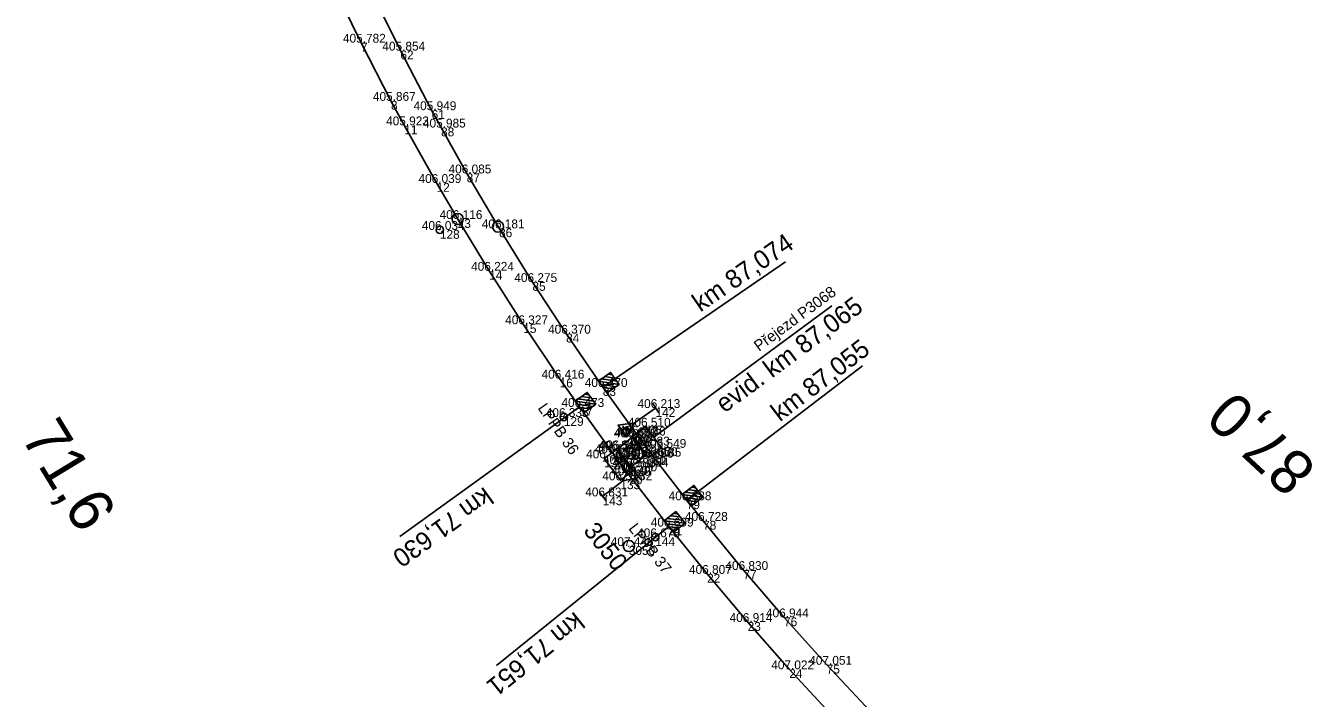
# Model space of a CAD drawing. Extents: x -663503 to -663109, y -1005607 to -1005191.
# Drawn here: x -663458.2 to -663283.9, y -1005429.6 to -1005338.4 of the extents above; entities that cross this region are included whole.
import ezdxf

# ---------------------------------------------------------------- set-up
doc = ezdxf.new("R2010")
doc.units = 0
for name, color, linetype in [('Vrstva 1', 7, 'Continuous'), ('Vrstva 27', 7, 'Continuous'), ('Vrstva 3', 7, 'Continuous'), ('Vrstva 4', 7, 'Continuous'), ('Vrstva 51', 7, 'Continuous'), ('Vrstva 60', 7, 'Continuous'), ('Vrstva 61', 7, 'Continuous'), ('Vrstva 63', 7, 'Continuous'), ('Vrstva 7', 7, 'Continuous')]:
    doc.layers.add(name, color=color, linetype=linetype)

msp = doc.modelspace()

# ---------------------------------------------------------------- linework, layer by layer
at = {"layer": 'Vrstva 1'}
for points in [[(-663416.55, -1005332.92), (-663412.77, -1005340.68), (-663408.71, -1005348.57), (-663406.91, -1005351.89), (-663402.53, -1005359.71), (-663399.67, -1005364.6), (-663395.4, -1005371.62), (-663390.78, -1005378.87), (-663385.85, -1005386.25), (-663383.15, -1005390.1), (-663378.63, -1005396.38), (-663377.54, -1005397.85), (-663376.41, -1005399.36), (-663371.04, -1005406.33), (-663365.87, -1005412.74), (-663360.37, -1005419.27), (-663354.73, -1005425.68), (-663349.15, -1005431.73)], [(-663343.71, -1005431.4), (-663349.66, -1005425.07), (-663355.44, -1005418.64), (-663360.94, -1005412.22), (-663366.41, -1005405.55), (-663368.63, -1005402.76), (-663373.21, -1005396.77), (-663374.28, -1005395.33), (-663375.38, -1005393.84), (-663380, -1005387.39), (-663384.97, -1005380.15), (-663389.54, -1005373.15), (-663394.06, -1005365.86), (-663398.45, -1005358.41), (-663401.92, -1005352.19), (-663403.2, -1005349.83), (-663407.43, -1005341.75), (-663411.05, -1005334.42)]]:
    msp.add_lwpolyline(points, dxfattribs=at)
at = {"layer": 'Vrstva 27'}
for p, q in [((-663385.3, -1005391.42), (-663385.25, -1005391.5)), ((-663372.92, -1005407.73), (-663372.86, -1005407.81))]:
    msp.add_line(p, q, dxfattribs=at)
for centre in [(-663385.28, -1005391.46), (-663372.89, -1005407.77)]:
    msp.add_circle(centre, 0.5, dxfattribs=at)
at = {"layer": 'Vrstva 3'}
for p, q in [((-663355.26, -1005370.41), (-663380, -1005387.39)), ((-663344.79, -1005384.54), (-663368.63, -1005402.76)), ((-663378.1, -1005386.61), (-663380.15, -1005386.27)), ((-663378.41, -1005386.18), (-663379.72, -1005385.96)), ((-663378.72, -1005385.74), (-663379.29, -1005385.65)), ((-663377.79, -1005387.04), (-663380.58, -1005386.58)), ((-663378.22, -1005387.35), (-663380.27, -1005387.01)), ((-663378.65, -1005387.66), (-663379.96, -1005387.44)), ((-663379.08, -1005387.96), (-663379.65, -1005387.87)), ((-663380.95, -1005389.74), (-663383.74, -1005389.29)), ((-663381.38, -1005390.05), (-663383.43, -1005389.72)), ((-663381.26, -1005389.31), (-663383.31, -1005388.98)), ((-663381.57, -1005388.88), (-663382.88, -1005388.67)), ((-663381.88, -1005388.45), (-663382.45, -1005388.36)), ((-663383.15, -1005390.1), (-663407.49, -1005407.65)), ((-663381.81, -1005390.37), (-663383.12, -1005390.15)), ((-663382.24, -1005390.68), (-663382.81, -1005390.58)), ((-663366.43, -1005402.33), (-663369.24, -1005401.97)), ((-663366.76, -1005401.91), (-663368.82, -1005401.65)), ((-663367.08, -1005401.49), (-663368.4, -1005401.32)), ((-663367.41, -1005401.07), (-663367.98, -1005401)), ((-663366.85, -1005402.65), (-663368.91, -1005402.39)), ((-663367.27, -1005402.98), (-663368.59, -1005402.81)), ((-663367.69, -1005403.3), (-663368.26, -1005403.23)), ((-663368.86, -1005405.85), (-663371.67, -1005405.55)), ((-663369.19, -1005405.44), (-663371.26, -1005405.21)), ((-663369.53, -1005405.02), (-663370.85, -1005404.88)), ((-663369.86, -1005404.61), (-663370.43, -1005404.55)), ((-663371.04, -1005406.33), (-663394.39, -1005425.16)), ((-663369.27, -1005406.18), (-663371.34, -1005405.96)), ((-663369.69, -1005406.51), (-663371.01, -1005406.37)), ((-663370.1, -1005406.85), (-663370.67, -1005406.78))]:
    msp.add_line(p, q, dxfattribs=at)
for points in [[(-663379.42, -1005388.2), (-663380.58, -1005386.58), (-663378.95, -1005385.41), (-663377.79, -1005387.04)], [(-663382.57, -1005390.91), (-663383.74, -1005389.29), (-663382.12, -1005388.12), (-663380.95, -1005389.74)], [(-663368.01, -1005403.55), (-663369.24, -1005401.97), (-663367.66, -1005400.75), (-663366.43, -1005402.33)], [(-663370.42, -1005407.1), (-663371.67, -1005405.55), (-663370.12, -1005404.29), (-663368.86, -1005405.85)]]:
    msp.add_lwpolyline(points, close=True, dxfattribs=at)
at = {"layer": 'Vrstva 4'}
for p, q in [((-663348.97, -1005376.37), (-663373.1, -1005394.2)), ((-663372.41, -1005390.88), (-663373.29, -1005389.6)), ((-663376.56, -1005393.09), (-663377.04, -1005393)), ((-663376.45, -1005399.22), (-663375.96, -1005399.28)), ((-663380.5, -1005401.61), (-663379.55, -1005402.84))]:
    msp.add_line(p, q, dxfattribs=at)
for points in [[(-663372.85, -1005390.24), (-663375.7, -1005392.23), (-663376.78, -1005394.19), (-663377.93, -1005392.56), (-663375.7, -1005392.23)], [(-663374.16, -1005392.77), (-663375.93, -1005394.08), (-663373.8, -1005396.98), (-663372.04, -1005395.64), (-663374.16, -1005392.77)], [(-663379.81, -1005397.07), (-663378.18, -1005395.92), (-663375.99, -1005398.83), (-663377.62, -1005400.05), (-663379.81, -1005397.07)], [(-663380.03, -1005402.23), (-663377.27, -1005400.11), (-663376.28, -1005398.1), (-663375.06, -1005399.68), (-663377.27, -1005400.11)]]:
    msp.add_lwpolyline(points, dxfattribs=at)
for centre in [(-663376.8, -1005393.04), (-663376.21, -1005399.25)]:
    msp.add_circle(centre, 0.248, dxfattribs=at)
at = {"layer": 'Vrstva 51'}
msp.add_lwpolyline([(-663378, -1005395.83), (-663376.06, -1005394.22), (-663374.22, -1005396.7), (-663376.2, -1005398.24), (-663378, -1005395.83)], dxfattribs=at)
at = {"layer": 'Vrstva 60'}
for p, q in [((-663412.77, -1005340.68), (-663412.77, -1005340.68)), ((-663407.43, -1005341.75), (-663407.43, -1005341.75)), ((-663408.71, -1005348.57), (-663408.71, -1005348.57)), ((-663403.2, -1005349.83), (-663403.2, -1005349.83)), ((-663406.91, -1005351.89), (-663406.91, -1005351.89)), ((-663401.92, -1005352.19), (-663401.92, -1005352.19)), ((-663398.45, -1005358.41), (-663398.45, -1005358.41)), ((-663402.53, -1005359.71), (-663402.53, -1005359.71)), ((-663399.67, -1005364.6), (-663399.67, -1005364.6)), ((-663402.08, -1005366.08), (-663402.08, -1005366.08)), ((-663394.06, -1005365.86), (-663394.06, -1005365.86)), ((-663395.4, -1005371.62), (-663395.4, -1005371.62)), ((-663389.54, -1005373.15), (-663389.54, -1005373.15)), ((-663390.78, -1005378.87), (-663390.78, -1005378.87)), ((-663384.97, -1005380.15), (-663384.97, -1005380.15)), ((-663385.85, -1005386.25), (-663385.85, -1005386.25)), ((-663380, -1005387.39), (-663380, -1005387.39)), ((-663385.28, -1005391.46), (-663385.28, -1005391.46)), ((-663383.15, -1005390.1), (-663383.15, -1005390.1)), ((-663372.85, -1005390.24), (-663372.85, -1005390.24)), ((-663374.16, -1005392.77), (-663374.16, -1005392.77)), ((-663376.06, -1005394.22), (-663376.06, -1005394.22)), ((-663375.93, -1005394.08), (-663375.93, -1005394.08)), ((-663375.38, -1005393.84), (-663375.38, -1005393.84)), ((-663378.63, -1005396.38), (-663378.63, -1005396.38)), ((-663378.18, -1005395.92), (-663378.18, -1005395.92)), ((-663378, -1005395.83), (-663378, -1005395.83)), ((-663374.28, -1005395.33), (-663374.28, -1005395.33)), ((-663374.22, -1005396.7), (-663374.22, -1005396.7)), ((-663373.21, -1005396.77), (-663373.21, -1005396.77)), ((-663372.04, -1005395.64), (-663372.04, -1005395.64)), ((-663379.81, -1005397.07), (-663379.81, -1005397.07)), ((-663377.54, -1005397.85), (-663377.54, -1005397.85)), ((-663376.2, -1005398.24), (-663376.2, -1005398.24)), ((-663373.8, -1005396.98), (-663373.8, -1005396.98)), ((-663377.62, -1005400.05), (-663377.62, -1005400.05)), ((-663376.41, -1005399.36), (-663376.41, -1005399.36)), ((-663375.99, -1005398.83), (-663375.99, -1005398.83)), ((-663380.03, -1005402.23), (-663380.03, -1005402.23)), ((-663368.63, -1005402.76), (-663368.63, -1005402.76)), ((-663366.41, -1005405.55), (-663366.41, -1005405.55)), ((-663371.04, -1005406.33), (-663371.04, -1005406.33)), ((-663376.47, -1005408.97), (-663376.47, -1005408.97)), ((-663372.89, -1005407.77), (-663372.89, -1005407.77)), ((-663360.94, -1005412.22), (-663360.94, -1005412.22)), ((-663365.87, -1005412.74), (-663365.87, -1005412.74)), ((-663360.37, -1005419.27), (-663360.37, -1005419.27)), ((-663355.44, -1005418.64), (-663355.44, -1005418.64)), ((-663354.73, -1005425.68), (-663354.73, -1005425.68)), ((-663349.66, -1005425.07), (-663349.66, -1005425.07))]:
    msp.add_line(p, q, dxfattribs=at)
at = {"layer": 'Vrstva 63'}
msp.add_line((-663376.5, -1005408.93), (-663376.44, -1005409.01), dxfattribs=at)
msp.add_circle((-663376.47, -1005408.97), 0.756, dxfattribs=at)
at = {"layer": 'Vrstva 7'}
msp.add_line((-663402.1, -1005366.04), (-663402.05, -1005366.13), dxfattribs=at)
for centre, radius in [((-663399.66, -1005364.61), 0.75), ((-663394.19, -1005365.63), 0.75), ((-663402.08, -1005366.08), 0.5)]:
    msp.add_circle(centre, radius, dxfattribs=at)

# ---------------------------------------------------------------- texts
at = {"layer": 'Vrstva 27'}
for s, rotation, p in [('LPPB 36', 304.9511, (-663388.88, -1005390.25)), ('LPPB 37', 307.6211, (-663376.59, -1005406.6))]:
    msp.add_text(s, height=1.5, rotation=rotation, dxfattribs=at).set_placement(p)
at = {"layer": 'Vrstva 3'}
for s, rotation, p in [('km 87,074', 34.4685, (-663366.78, -1005377.29)), ('km 87,055', 37.4, (-663356.01, -1005392.18)), ('km 71,630', 215.7883, (-663396.06, -1005400.85)), ('km 71,651', 218.892, (-663383.82, -1005417.77))]:
    msp.add_text(s, height=2.5, rotation=rotation, dxfattribs=at).set_placement(p)
at = {"layer": 'Vrstva 4'}
for s, height, p in [('Přejezd P3068', 1.5, (-663358.83, -1005382.62)), ('evid. km 87,065', 2.5, (-663363.51, -1005390.99))]:
    msp.add_text(s, height=height, rotation=36.4743, dxfattribs=at).set_placement(p)
at = {"layer": 'Vrstva 51'}
msp.add_text('živ.', height=1.5, rotation=306.5255, dxfattribs=at).set_placement((-663377.28, -1005395.68))
at = {"layer": 'Vrstva 60'}
for s, p in [('7', (-663412.77, -1005341.88)), ('62', (-663407.43, -1005342.95)), ('8', (-663408.71, -1005349.77)), ('61', (-663403.2, -1005351.03)), ('11', (-663406.91, -1005353.09)), ('88', (-663401.92, -1005353.39)), ('87', (-663398.45, -1005359.61)), ('12', (-663402.53, -1005360.91)), ('13', (-663399.67, -1005365.8)), ('128', (-663402.08, -1005367.28)), ('86', (-663394.06, -1005367.07)), ('14', (-663395.4, -1005372.82)), ('85', (-663389.54, -1005374.34)), ('15', (-663390.78, -1005380.07)), ('84', (-663384.97, -1005381.35)), ('16', (-663385.85, -1005387.45)), ('83', (-663380, -1005388.59)), ('129', (-663385.28, -1005392.66)), ('17', (-663383.15, -1005391.3)), ('142', (-663372.85, -1005391.44)), ('136', (-663374.16, -1005393.97)), ('138', (-663376.06, -1005395.42)), ('137', (-663375.93, -1005395.28)), ('82', (-663375.38, -1005395.04)), ('18', (-663378.63, -1005397.58)), ('131', (-663378.18, -1005397.12)), ('139', (-663378, -1005397.03)), ('81', (-663374.28, -1005396.54)), ('141', (-663374.22, -1005397.9)), ('80', (-663373.21, -1005397.97)), ('135', (-663372.04, -1005396.84)), ('130', (-663379.81, -1005398.27)), ('19', (-663377.54, -1005399.05)), ('140', (-663376.2, -1005399.44)), ('134', (-663373.8, -1005398.18)), ('133', (-663377.62, -1005401.25)), ('20', (-663376.41, -1005400.57)), ('132', (-663375.99, -1005400.03)), ('143', (-663380.03, -1005403.43)), ('79', (-663368.63, -1005403.96)), ('78', (-663366.41, -1005406.75)), ('21', (-663371.04, -1005407.53)), ('3050', (-663376.47, -1005410.17)), ('144', (-663372.89, -1005408.97)), ('77', (-663360.94, -1005413.42)), ('22', (-663365.87, -1005413.94)), ('23', (-663360.37, -1005420.47)), ('76', (-663355.44, -1005419.84)), ('24', (-663354.73, -1005426.88)), ('75', (-663349.66, -1005426.27))]:
    msp.add_text(s, height=1.2, dxfattribs=at).set_placement(p)
at = {"layer": 'Vrstva 61'}
for s, p in [('405.782', (-663415.22, -1005340.68)), ('405.854', (-663409.88, -1005341.75)), ('405.867', (-663411.16, -1005348.57)), ('405.949', (-663405.65, -1005349.83)), ('405.923', (-663409.37, -1005351.89)), ('405.985', (-663404.38, -1005352.19)), ('406.039', (-663404.98, -1005359.71)), ('406.085', (-663400.91, -1005358.41)), ('406.116', (-663402.12, -1005364.6)), ('406.034', (-663404.53, -1005366.08)), ('406.181', (-663396.41, -1005365.86)), ('406.224', (-663397.85, -1005371.62)), ('406.275', (-663391.99, -1005373.15)), ('406.327', (-663393.23, -1005378.87)), ('406.370', (-663387.42, -1005380.15)), ('406.416', (-663388.3, -1005386.25)), ('406.470', (-663382.45, -1005387.39)), ('406.473', (-663385.61, -1005390.1)), ('406.213', (-663375.3, -1005390.24)), ('406.335', (-663387.73, -1005391.46)), ('406.510', (-663376.61, -1005392.77)), ('406.655', (-663378.51, -1005394.22)), ('406.657', (-663378.39, -1005394.08)), ('406.565', (-663377.83, -1005393.84)), ('406.542', (-663380.63, -1005395.92)), ('406.562', (-663380.45, -1005395.83)), ('406.583', (-663376.73, -1005395.33)), ('406.549', (-663374.49, -1005395.64)), ('406.564', (-663382.26, -1005397.07)), ('406.565', (-663381.09, -1005396.38)), ('406.584', (-663379.99, -1005397.85)), ('406.686', (-663376.67, -1005396.7)), ('406.696', (-663376.25, -1005396.98)), ('406.600', (-663375.66, -1005396.77)), ('406.597', (-663378.86, -1005399.36)), ('406.588', (-663378.66, -1005398.24)), ('406.580', (-663378.44, -1005398.83)), ('406.575', (-663380.07, -1005400.05)), ('406.831', (-663382.38, -1005402.23)), ('406.688', (-663371.08, -1005402.76)), ('406.699', (-663373.5, -1005406.33)), ('406.728', (-663368.87, -1005405.55)), ('406.678', (-663375.35, -1005407.77)), ('407.446', (-663378.92, -1005408.97)), ('406.807', (-663368.32, -1005412.74)), ('406.830', (-663363.39, -1005412.22)), ('406.944', (-663357.89, -1005418.64)), ('406.914', (-663362.82, -1005419.27)), ('407.022', (-663357.17, -1005425.68)), ('407.051', (-663352.02, -1005425.07))]:
    msp.add_text(s, height=1.2, dxfattribs=at).set_placement(p)
at = {"layer": 'Vrstva 63'}
msp.add_text('3050', height=2.4, rotation=307.6211, dxfattribs=at).set_placement((-663382.73, -1005406.91))
at = {"layer": 'Vrstva 7'}
for s, rotation, p in [('87,0', 137.1454, (-663283.03, -1005398.22)), ('71,6', 301.3331, (-663458.96, -1005394.15))]:
    msp.add_text(s, height=6, rotation=rotation, dxfattribs=at).set_placement(p)

doc.saveas('drawing.dxf')
